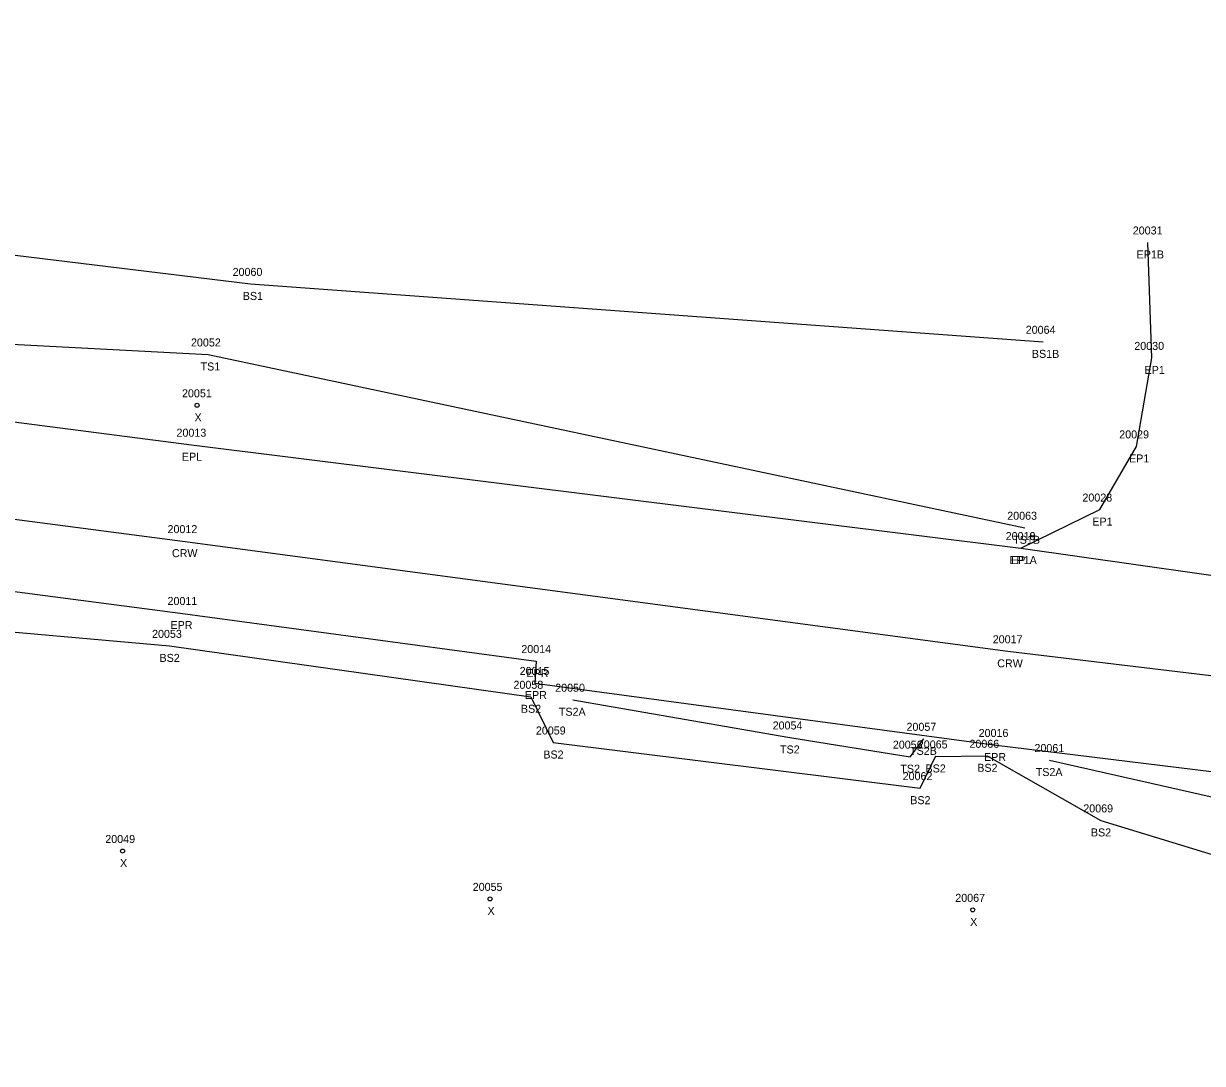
# Model space of a CAD drawing. Extents: x 2080935 to 2082049, y 730754 to 730962.
# Drawn here: x 2081229.8 to 2081377.1, y 730830 to 730959.9 of the extents above; entities that cross this region are included whole.
import ezdxf

# ---------------------------------------------------------------- set-up
doc = ezdxf.new("R2010")
doc.units = 0
for name, color, linetype in [('RD_DTM_BkLn1', 7, 'Continuous'), ('RD_DTM_BkLn2', 7, 'Continuous'), ('RD_EX_Road', 7, 'Continuous'), ('RD_EX_Road_txCode', 7, 'Continuous'), ('RD_Sketch8', 7, 'Continuous'), ('RD_SMD_Locator', 7, 'Continuous'), ('RD_SMD_Misc', 7, 'Continuous')]:
    doc.layers.add(name, color=color, linetype=linetype)

msp = doc.modelspace()

# ---------------------------------------------------------------- linework, layer by layer
at = {"layer": 'RD_DTM_BkLn1'}
msp.add_lwpolyline([(2080941.25, 730935.08), (2081045.42, 730921.9), (2081147.52, 730908.57), (2081249.67, 730895.22), (2081352.74, 730881.46), (2081412.15, 730874.37), (2081469.7, 730866.51)], dxfattribs=at)
at = {"layer": 'RD_DTM_BkLn2'}
for points in [[(2080945.43, 730959.86), (2081048.27, 730948.4), (2081150.46, 730940.47), (2081258.15, 730927.34), (2081357.17, 730920.11)], [(2080943.5, 730950.5), (2081046.79, 730938.49), (2081149.23, 730923.98), (2081252.89, 730918.53), (2081354.86, 730896.89)], [(2080937.44, 730917.14), (2081043.42, 730899.5), (2081145.18, 730884.99), (2081213.57, 730879.31), (2081219.84, 730884.63), (2081248.03, 730882.14), (2081293.17, 730875.78), (2081295.97, 730870.07), (2081341.8, 730864.37), (2081343.7, 730868.33), (2081350.17, 730868.41), (2081364.36, 730860.34), (2081384.26, 730854.27), (2081383.97, 730833.2)], [(2081298.42, 730875.41), (2081325.54, 730870.7), (2081340.57, 730868.3), (2081342.26, 730870.53)], [(2081357.97, 730867.88), (2081387.21, 730861.23), (2081392.06, 730852.12), (2081407.42, 730829.99)]]:
    msp.add_lwpolyline(points, dxfattribs=at)
at = {"layer": 'RD_EX_Road'}
for points in [[(2080942.12, 730947.38), (2081047.3, 730933.82), (2081149.12, 730920.41), (2081250.8, 730907.26), (2081354.36, 730894.35), (2081413.29, 730885.99), (2081474.17, 730877.58), (2081469.7, 730866.51)], [(2081354.36, 730894.35), (2081364.23, 730899.16), (2081368.82, 730907.05), (2081370.75, 730918.1), (2081370.23, 730932.52)], [(2080939.88, 730923.83), (2081043.62, 730910.24), (2081146.95, 730896.77), (2081220.01, 730886.78), (2081221.02, 730889.92), (2081249.39, 730886.24), (2081293.86, 730880.24), (2081293.66, 730877.5), (2081351.01, 730869.76), (2081411.83, 730862.33), (2081465.27, 730855.52), (2081469.7, 730866.51)]]:
    msp.add_lwpolyline(points, dxfattribs=at)
at = {"layer": 'RD_SMD_Locator'}
for centre, radius in [((2081370.23, 730932.52), 0.001), ((2081258.15, 730927.34), 0.001), ((2081357.17, 730920.11), 0.001), ((2081252.89, 730918.53), 0.001), ((2081370.75, 730918.1), 0.001), ((2081251.49, 730912.18), 0.25), ((2081250.8, 730907.26), 0.001), ((2081368.82, 730907.05), 0.001), ((2081364.23, 730899.16), 0.001), ((2081354.86, 730896.89), 0.001), ((2081249.67, 730895.22), 0.001), ((2081354.36, 730894.35), 0.001), ((2081354.36, 730894.35), 0.001), ((2081249.39, 730886.24), 0.001), ((2081248.03, 730882.14), 0.001), ((2081352.74, 730881.46), 0.001), ((2081293.86, 730880.24), 0.001), ((2081293.66, 730877.5), 0.001), ((2081293.17, 730875.78), 0.001), ((2081298.42, 730875.41), 0.001), ((2081295.97, 730870.07), 0.001), ((2081325.54, 730870.7), 0.001), ((2081342.26, 730870.53), 0.001), ((2081351.01, 730869.76), 0.001), ((2081340.57, 730868.3), 0.001), ((2081343.7, 730868.33), 0.001), ((2081350.17, 730868.41), 0.001), ((2081357.97, 730867.88), 0.001), ((2081341.8, 730864.37), 0.001), ((2081364.36, 730860.34), 0.001), ((2081242.18, 730856.52), 0.25), ((2081288.08, 730850.54), 0.25), ((2081348.37, 730849.17), 0.25)]:
    msp.add_circle(centre, radius, dxfattribs=at)

# ---------------------------------------------------------------- texts
at = {"layer": 'RD_EX_Road_txCode'}
for s, p in [('20031', (2081368.36, 730933.52)), ('EP1B', (2081368.84, 730930.52)), ('20030', (2081368.55, 730919.1)), ('EP1', (2081369.83, 730916.1)), ('20013', (2081248.92, 730908.26)), ('20029', (2081366.67, 730908.05)), ('EPL', (2081249.59, 730905.26)), ('EP1', (2081367.9, 730905.05)), ('20028', (2081362.07, 730900.16)), ('EP1', (2081363.31, 730897.16)), ('20018', (2081352.49, 730895.35)), ('20019', (2081352.49, 730895.35)), ('EP1A', (2081352.95, 730892.35)), ('EPL', (2081353.16, 730892.35)), ('20011', (2081247.8, 730887.24)), ('EPR', (2081248.17, 730884.24)), ('20014', (2081291.99, 730881.24)), ('20015', (2081291.78, 730878.5)), ('EPR', (2081292.63, 730878.24)), ('EPR', (2081292.43, 730875.5)), ('20016', (2081349.11, 730870.76)), ('EPR', (2081349.78, 730867.76))]:
    msp.add_text(s, height=1, dxfattribs=at).set_placement(p)
at = {"layer": 'RD_Sketch8'}
for s, p in [('20051', (2081249.61, 730913.18)), ('X', (2081251.17, 730910.18)), ('20049', (2081240.03, 730857.52)), ('X', (2081241.87, 730854.52)), ('20055', (2081285.92, 730851.54)), ('20067', (2081346.19, 730850.17)), ('X', (2081287.77, 730848.54)), ('X', (2081348.05, 730847.17))]:
    msp.add_text(s, height=1, dxfattribs=at).set_placement(p)
at = {"layer": 'RD_SMD_Misc'}
for s, p in [('20060', (2081255.93, 730928.34)), ('BS1', (2081257.2, 730925.34)), ('20064', (2081354.99, 730921.11)), ('20052', (2081250.73, 730919.53)), ('BS1B', (2081355.76, 730918.11)), ('TS1', (2081251.93, 730916.53)), ('20063', (2081352.68, 730897.89)), ('20012', (2081247.8, 730896.22)), ('TS1B', (2081353.42, 730894.89)), ('CRW', (2081248.35, 730893.22)), ('20053', (2081245.87, 730883.14)), ('20017', (2081350.87, 730882.46)), ('BS2', (2081246.8, 730880.14)), ('CRW', (2081351.43, 730879.46)), ('20058', (2081291.01, 730876.78)), ('20050', (2081296.22, 730876.41)), ('BS2', (2081291.94, 730873.78)), ('TS2A', (2081296.68, 730873.41)), ('20054', (2081323.38, 730871.7)), ('20057', (2081340.1, 730871.53)), ('20059', (2081293.81, 730871.07)), ('TS2', (2081324.3, 730868.7)), ('20056', (2081338.39, 730869.3)), ('TS2B', (2081340.54, 730868.53)), ('20065', (2081341.51, 730869.33)), ('20066', (2081347.96, 730869.41)), ('20061', (2081356.08, 730868.88)), ('BS2', (2081294.74, 730868.07)), ('TS2', (2081339.33, 730866.3)), ('BS2', (2081342.47, 730866.33)), ('BS2', (2081348.94, 730866.41)), ('TS2A', (2081356.24, 730865.88)), ('20062', (2081339.62, 730865.37)), ('BS2', (2081340.57, 730862.37)), ('20069', (2081362.18, 730861.34)), ('BS2', (2081363.13, 730858.34))]:
    msp.add_text(s, height=1, dxfattribs=at).set_placement(p)

doc.saveas('drawing.dxf')
